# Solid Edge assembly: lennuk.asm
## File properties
Author: Georg
Template: Iso Metric Assembly.asm
Last saved by: Georg
Revision: 20
Application: Solid Edge
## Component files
propeller.par
kere.par
tiivad.par
alus.psm
katus.par
kp_alus.par
kuulipilduri_haoidja.par
kp_toru.par
kp_vahend.par
relvatoru.par
tool.par
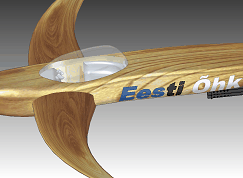
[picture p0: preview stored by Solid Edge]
